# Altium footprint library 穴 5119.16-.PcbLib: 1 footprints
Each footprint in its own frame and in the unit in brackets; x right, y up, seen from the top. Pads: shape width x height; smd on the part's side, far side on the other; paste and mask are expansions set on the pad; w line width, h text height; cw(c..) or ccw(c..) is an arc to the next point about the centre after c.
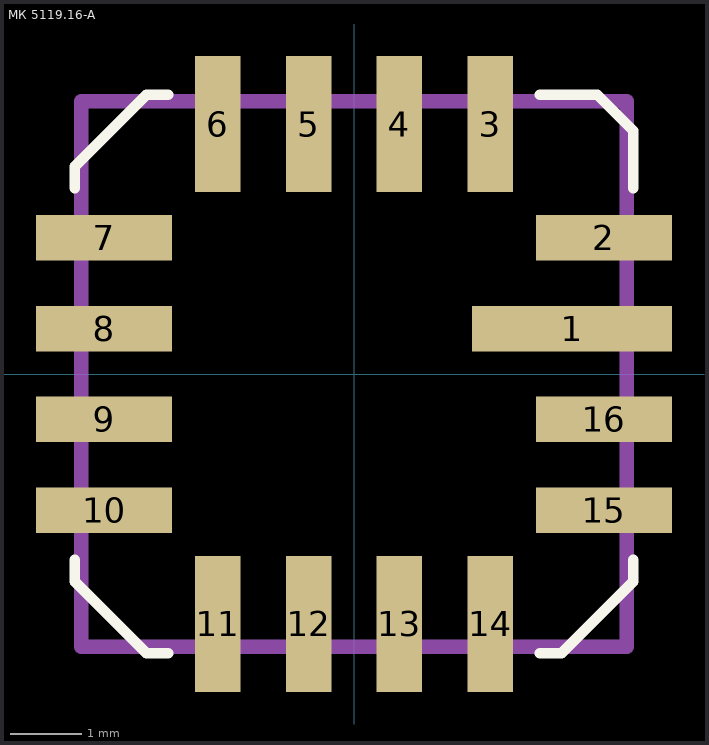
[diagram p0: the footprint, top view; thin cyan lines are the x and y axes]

## МК 5119.16-A [mil] "Микромеханический датчик удара"
pads (16):
  rect 110x25 smd: 1(120,25)
  rect 75x25 smd: 2(137.5,75) 7(-137.5,75) 8(-137.5,25) 9(-137.5,-25) 10(-137.5,-75) 15(137.5,-75) 16(137.5,-25)
  rect 25x75 smd: 3(75,137.5) 4(25,137.5) 5(-25,137.5) 6(-75,137.5) 11(-75,-137.5) 12(-25,-137.5) 13(25,-137.5) 14(75,-137.5)
Top Overlay:
  lines w5.91: -153.54,-102.36 -153.54,-114.17 -114.17,-153.54 -102.36,-153.54 ; -153.54,102.36 -153.54,114.17 -114.17,153.54 -102.36,153.54 ; 102.36,-153.54 114.17,-153.54 153.54,-114.17 153.54,-102.36 ; 102.36,153.54 133.86,153.54 153.54,133.86 153.54,102.36
Top Courtyard:
  lines w7.87: -150,-150 150,-150 150,150 -150,150 -150,-150
3D body "МК 5119.16-A.step": height 95.24, standoff 0, extent -150,-150 150,150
